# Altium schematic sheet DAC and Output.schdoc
size 297 x 209 mm; Symbol: Drawing-Symbol_A4; @Project Name: Pedal Steel; @Page Count: 1; @Update Date: 2026-10-20; @Create Date: 2026-10-20; @Schematic Name: Schematic1; @Page No: 1; @Page Name: P1; Company: EasyEDA.com; Version: V1.0; Page Size: A4; Device: Drawing-Symbol_A4; @Create Time: 17:30:55; @Update Time: 17:30:55; Border: 1; Width: 1170; Height: 825; Region Start: 1; X Region Count: 6; Y Region Count: 4; Blade Width: 10; Title Block Position: 3
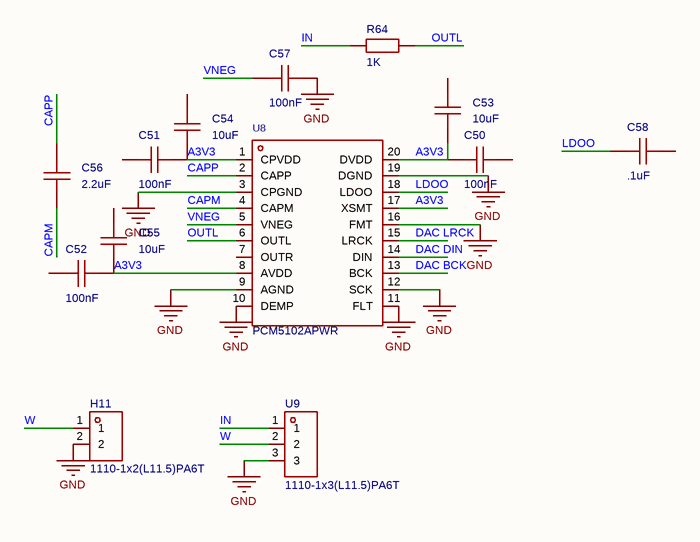
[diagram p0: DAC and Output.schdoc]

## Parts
C50  100nF  [C0603]
C51  100nF  [C0603]
C52  100nF  [C0603]
C53  10uF  [C0603]
C54  10uF  [C0603]
C55  10uF  [C0603]
C56  2.2uF  [C0603]
C57  100nF  [C0603]
C58  .1uF  [C0603]
H11  1110-1x2(L11.5)PA6T  [HDR-TH_2P-P2.54-H-M-W9.0]
R64  1K  [R0603]
U8  PCM5102APWR  [TSSOP-20_L6.5-W4.4-P0.65-LS6.4-BL]
U9  1110-1x3(L11.5)PA6T  [HDR-TH_3P-P2.54-H-M-W8.0]

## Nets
GND: C57.1 H11.2 U8.3(CPGND) U8.9(AGND) U8.10(DEMP) U8.11(FLT) U8.12(SCK) U8.16(FMT) U8.19(DGND) U9.3
A3V3: C50.2 C51.1 C52.1 C53.2 C54.2 C55.2 U8.1(CPVDD) U8.8(AVDD) U8.17(XSMT) U8.20(DVDD)
CAPM: C56.2 U8.4(CAPM)
CAPP: C56.1 U8.2(CAPP)
DAC BCK: U8.13(BCK)
DAC DIN: U8.14(DIN)
DAC LRCK: U8.15(LRCK)
IN: R64.1 U9.1
LDOO: C58.2 U8.18(LDOO)
OUTL: R64.2 U8.6(OUTL)
VNEG: C57.2 U8.5(VNEG)
W: H11.1 U9.2

Not connected (* = marked no-connect by the designer): C50 1; C51 2; C52 2; C53 1; C54 1; C55 1; C58 1; U8 7(OUTR)

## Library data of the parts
C50-C58 = CAP_0603: Symbol: CAP_OLD; ConvertToPcb: yes; ModelId: 624118aa3cc7497086c383c2d72e08520819f05c4eef4c71ace90d822a990e87; ModelName: C0603_L1.6-W0.8-H0.8; ModelTransform: 62.992,31.496,0,0,0,0,0,0,0
H11 = 1110-1x2(L11.5)PA6T: Pin Structure:1x2P Pitch:2.54mm Circluar Pins/Square Pins:Square pin Mounting Type:Right Angle Number of Rows:1 Number of Pins:2P Current Rating:3A Voltage Rating (Max):250V Length of Mating Pin:3.5mm Insulation Height:2.54mm Contact Material:Brass Contac; Manufacturer: CST(永丰盈); AddInBom: yes; ModelId: 7248d4bf3ef34400a5851ce875e9671e0819f05c4eef4c71ace90d822a990e87; ModelTransform: 196.063,354.33,0,0,0,0,0,-165.354,-118.11; Pin Structure: 1x2P; Pitch: 2.54mm; Current Rating: 3A; Voltage Rating (Max): 250V
R64 = Res_0603: Symbol: Res; ConvertToPcb: yes; ModelId: 112863783b5b41f1b5254f87eedc79320819f05c4eef4c71ace90d822a990e87; ModelTransform: 31.8897,63.7794,0,90,0,0,0,0,0
U8 = PCM5102APWR: Resolution (Bits):32 Number of Channels:2 Voltage - Supply:1.8V~3.3V Voltage - Supply:1.8V~3.3V Interface Type:I2S The Chip Type:Audio Decoder Operating Temperature:-25℃~+85℃ Operating Temperature:-25℃~+85℃ Sampling Rate:384kHz Quiescent Current (Iq):500u; Manufacturer: TI(德州仪器); AddInBom: yes; ModelId: d00c537554e8428abe371c2c4fe2166f0819f05c4eef4c71ace90d822a990e87; ModelName: TSSOP-20_L6.5-W4.4-H1.0-LS6.4-P0.65; ModelTransform: 251.969,255.906,0,90,0,0,0.0005,0,0; Resolution (Bits): 32; Number of Channels: 2; Interface Type: I2S; Sampling Rate: 384kHz; Quiescent Current (Iq): 500uA
U9 = 1110-1x3(L11.5)PA6T: Pin Structure:1x3P Pitch:2.54mm Circluar Pins/Square Pins:Pin Header Mounting Type:Right Angle Number of Rows:1 Number of Pins:3P Current Rating:3A Voltage Rating (Max):250V Length of Mating Pin:3.5mm Insulation Height:2.54mm Contact Material:Brass Contac; Manufacturer: CST(永丰盈); AddInBom: yes; ModelId: 8af6a733bb33433f90d20139532c28540819f05c4eef4c71ace90d822a990e87; ModelTransform: 300.3931,314.96,0,0,0,0,0,-143.701,-118.11; Pin Structure: 1x3P; Pitch: 2.54mm; Current Rating: 3A; Voltage Rating (Max): 250V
